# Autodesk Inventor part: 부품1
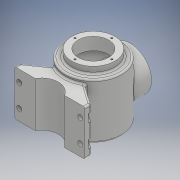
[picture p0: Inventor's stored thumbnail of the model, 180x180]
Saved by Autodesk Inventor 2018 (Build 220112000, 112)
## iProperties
Created: 2021-04
Part Number: 부품1
Material: Generic
Document SubType Name: Modeling
Designer: theplan76
Density: 1 g/cm^3
Appearance: Default
Author: theplan76
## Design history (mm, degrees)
sketch "스케치1"
  geometry: C1 r 50 at (0, 0); 1 further point
  constraints: 1 centre point, 1 coincident
  dimensions: "d0" = 100 diameter of C1
extrude "돌출1" new body sketch "스케치1" stored distance "d1" = 108; taper "d2" = 0 deg
sketch "스케치2"
  geometry: C1 r 38 at (0, 0); 1 further point
  constraints: 1 centre point, 1 coincident
  dimensions: "d3" = 76 diameter of C1
extrude "돌출2" join sketch "스케치2" distance "d4" = 12; taper "d5" = 0 deg
sketch "스케치3"
  geometry: C1 r 27 at (0, 0); 1 further point
  constraints: 1 centre point, 1 coincident
  dimensions: "d6" = 54 diameter of C1
extrude "돌출3" cut sketch "스케치3" distance "d7" = 22; taper "d8" = 0 deg
node "작업 평면1"
sketch "스케치5"
  geometry: L1 (38, 66)-(-38, 66) reference; C1 r 38 at (0, 4); 1 further point
  constraints: 1 centre point
  dimensions: "d16" = 62 distance from line of C1.centre L1; "d17" = 76 diameter of C1; "d18" = 72.71864 distance of L1.start C1.centre
extrude "돌출5" join sketch "스케치5" stored distance "d14" = 65; taper "d15" = 0 deg
sketch "스케치7"
  geometry: L1 (-38, -62)-(38, -62) reference; C1 r 27 at (0, 0); 1 further point
  constraints: 1 centre point, 1 vertical alignment
  dimensions: "d21" = 62 distance from line of C1.centre L1; "d50" = 54 diameter of C1
extrude "돌출6" cut sketch "스케치7" distance "d22" = 46.75; taper "d23" = 0 deg
sketch "스케치8" dims "d25" = 65
  geometry: 3 further points
  constraints: 2 horizontal alignment, 2 other
  dimensions: "d26" = 4 distance of point (0, 4) point (0, 0); "d27" = 32.74523 distance of point (0, 4) point (-32.5, 0)
hole "구멍1" sketch "스케치8" at (-32.5, 0) diameter "d28" = 3.242; stored, may be unused: countersink angle "d32" = 90 deg, drill point angle "d34" = 118 deg; dims "d29" = 8, "d30" = 4, "d31" = 2, "d33" = 10
sketch "스케치9" dims "d38" = 65
  geometry: 3 further points
  constraints: 2 vertical alignment, 1 coincident, 2 other
hole "구멍2" sketch "스케치9" at (0, 32.5) diameter "d39" = 3.242; stored, may be unused: countersink angle "d43" = 90 deg, drill point angle "d45" = 118 deg; dims "d40" = 8, "d41" = 4, "d42" = 2, "d44" = 10
node "작업 평면2"
sketch "스케치25"
  geometry: 1 further point
fillet "모깎기1" dims "d80" = 3
sketch "스케치32"
  geometry: L1 (-50, -54)-(50, -54) reference; L2 (50, -54)-(50, 51) reference; L3 (50, -42.336)-(50, -54); L4 (0, -54)-(50, -54); L5 (0, -54)-(0, -69.075); A1 r 113 centre (0, 59) between (0, -54) and (50, -42.336); 1 further point
  constraints: 6 end point, 2 collinear, 2 point on circle, 1 centre point, 1 midpoint, 1 point on line, 1 tangent, 1 vertical
  dimensions: "d89" = 113 radius of A1
revolve "회전1" sketch "스케치32" stored, may be unused: angle "d90" = 90 deg
sketch "스케치33"
  geometry: L1 (-27, 44)-(27, 44) reference; L2 (0, 44)-(40, 44); L3 (40, 44)-(40, -35.916); L4 (0, -44)-(0, 44); L5 (50, -42.336)-(-50, -42.336) reference; A1 r 103 centre (0, 59) between (0, -44) and (40, -35.916); A2 r 113 centre (0, 59) between (-50, -42.336) and (50, -42.336) reference; 1 further point
  constraints: 6 end point, 2 point on circle, 1 centre point, 1 concentric, 1 horizontal, 1 midpoint, 1 parallel, 1 perpendicular, 1 point on line
  dimensions: "d91" = 103 radius of A1; "d92" = 80 diameter of L3 L4
revolve "회전2" sketch "스케치33" stored, may be unused: angle "d94" = 90 deg
node "작업 평면3"
sketch "스케치34"
  geometry: L1 (-26.694, -42.278)-(-62, -67); L2 (-62, -67)-(-62, -77); L3 (-62, -77)-(62, -77); L4 (62, -77)-(62, -67); L5 (62, -67)-(26.694, -42.278); L6 (-38, 65)-(38, 65) reference; C1 r 27 at (0, 0) reference; C2 r 27 at (0, 0) reference; A1 r 50 centre (0, 0) between (-26.694, -42.278) and (26.694, -42.278) reference; A2 r 50 centre (0, 0) between (-26.694, -42.278) and (26.694, -42.278) reference; A3 r 50 centre (0, 0) between (-26.694, -42.278) and (26.694, -42.278); 3 further points
  constraints: 10 end point, 3 point on circle, 2 vertical, 1 centre point, 1 concentric, 1 midpoint, 1 parallel, 1 vertical alignment, 2 other
  dimensions: "d97" = 55 deg angle of L2 L1; "d98" = 55 deg angle of L4 L5; "d99" = 124 distance of L2.end L3.end; "d100" = 10 distance of L3.end L4.end; "d101" = 10 distance of L1.end L2.end; "d103" = 77 distance from line of point (0, 0) L3
extrude "돌출11" join sketch "스케치34" distance "d104" = 80; taper "d105" = 0 deg
sketch "스케치35"
  geometry: L1 (-62, -77)-(62, -77) reference; C1 r 30 at (0, -92); 1 further point
  constraints: 1 centre point, 1 vertical alignment
  dimensions: "d106" = 15 distance centre to line of C1 L1; "d107" = 60 diameter of C1
extrude "돌출12" cut sketch "스케치35" extent not by distance; stored distance "d108" = 80; taper "d109" = 0 deg
fillet "모깎기5" dims "d110" = 3
fillet "모깎기6" dims "d111" = 3
fillet "모깎기7" dims "d112" = 3
sketch "스케치36"
  geometry: L1 (0, 80)-(33.019, 80) reference; L2 (36.019, 77)-(36.019, 3) reference; 2 further points
  dimensions: "d113" = 20 distance from line of L1 point (28.019, 60); "d114" = 8 distance from line of L2 point (28.019, 60)
hole "구멍3" sketch "스케치36" at (28.019, 60) diameter "d115" = 9; stored, may be unused: countersink angle "d119" = 90 deg, drill point angle "d121" = 0 deg; dims "d116" = 6, "d117" = 9, "d118" = 2, "d120" = 6
sketch "스케치37"
  geometry: L1 (0, 0)-(30.96, 0); L2 (0, -7)-(30.96, -7); L3 (30.96, 7)-(0, 7); C1 r 4.5 at (0, 0) reference; A1 r 7 centre (0, 0) between (0, 7) and (0, -7); A2 r 7 centre (30.96, 0) between (30.96, -7) and (30.96, 7); 2 further points
  constraints: 8 end point, 4 point on circle, 4 tangent, 2 centre point, 1 horizontal, 1 midpoint, 1 parallel
  dimensions: "d122" = 7 radius of A2; "d123" = 91.1436 distance of point (-54, -26) L3.start
extrude "돌출13" cut sketch "스케치37" distance "d124" = 46.75; taper "d125" = 0 deg
node "작업 평면4"
node "작업 평면5"
sketch "스케치38"
  geometry: 2 further points
  constraints: 1 coincident, 1 other
feature "엠보싱1" sketch "스케치38" dims "d127" = 0.5, "d128" = 0
node "솔리드1"
pattern_circular "원형 패턴1" dims angle "d36" = 360 deg
pattern_circular "원형 패턴2" dims angle "d47" = 360 deg
mirror "미러1"
mirror "미러2"
node "투영된 루프1"
node "절단 모서리 투영1"
node "절단 모서리 투영2"
other parameters: "d12" = 65, "d49" = -77, "d126" = -108
